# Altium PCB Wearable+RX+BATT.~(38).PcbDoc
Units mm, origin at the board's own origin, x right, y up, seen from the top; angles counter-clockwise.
Board outline 26 x 26 mm, 2 copper layers (Top, Bottom), stack 0.323 mm thick; 66 components, 48 nets, 228 pads, 162 vias.
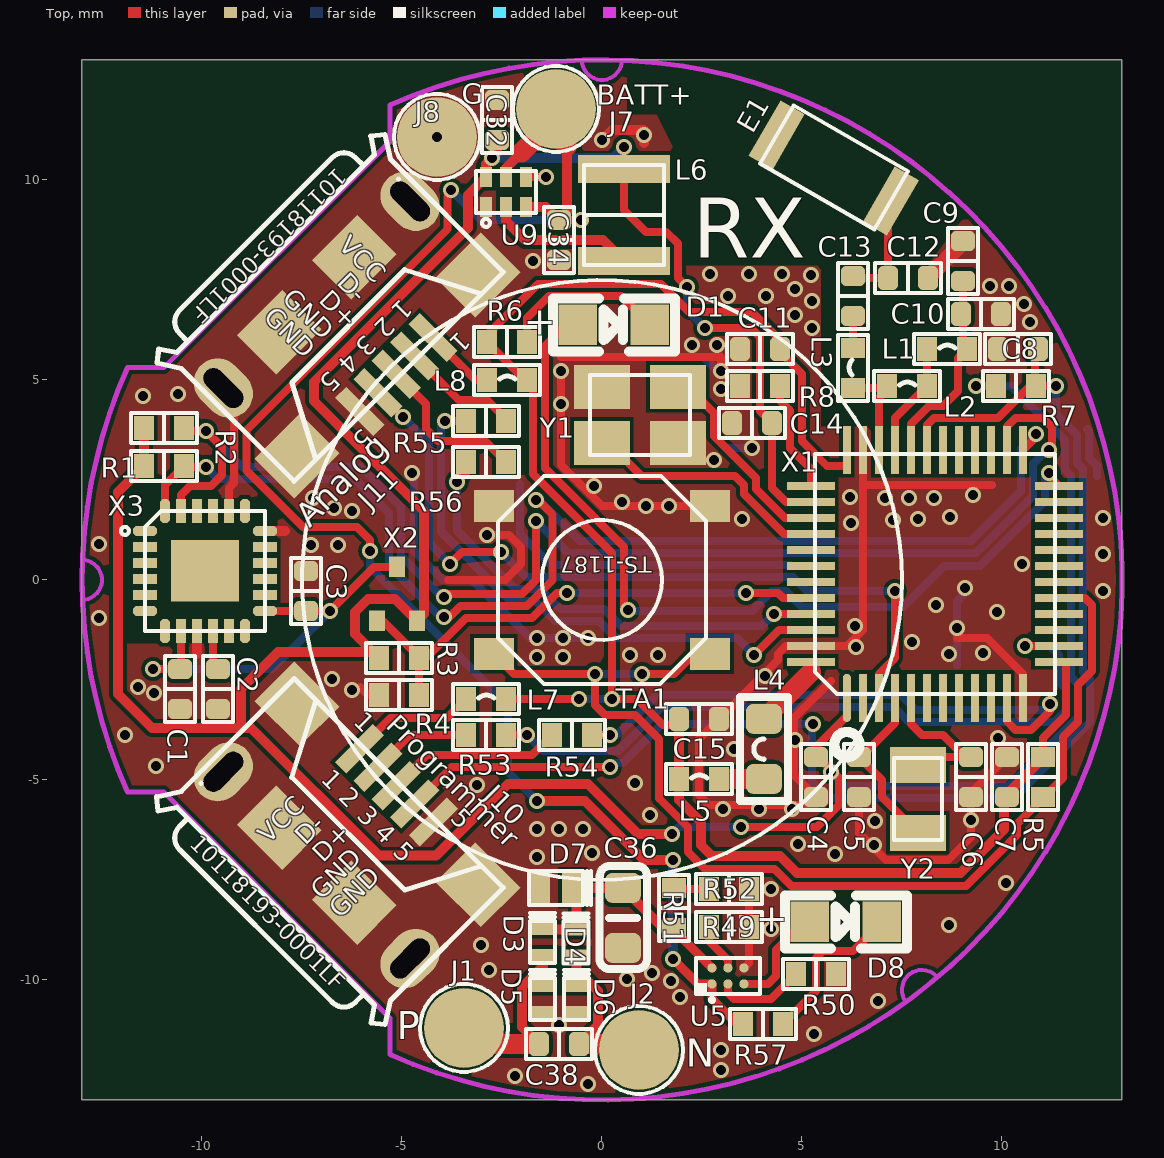
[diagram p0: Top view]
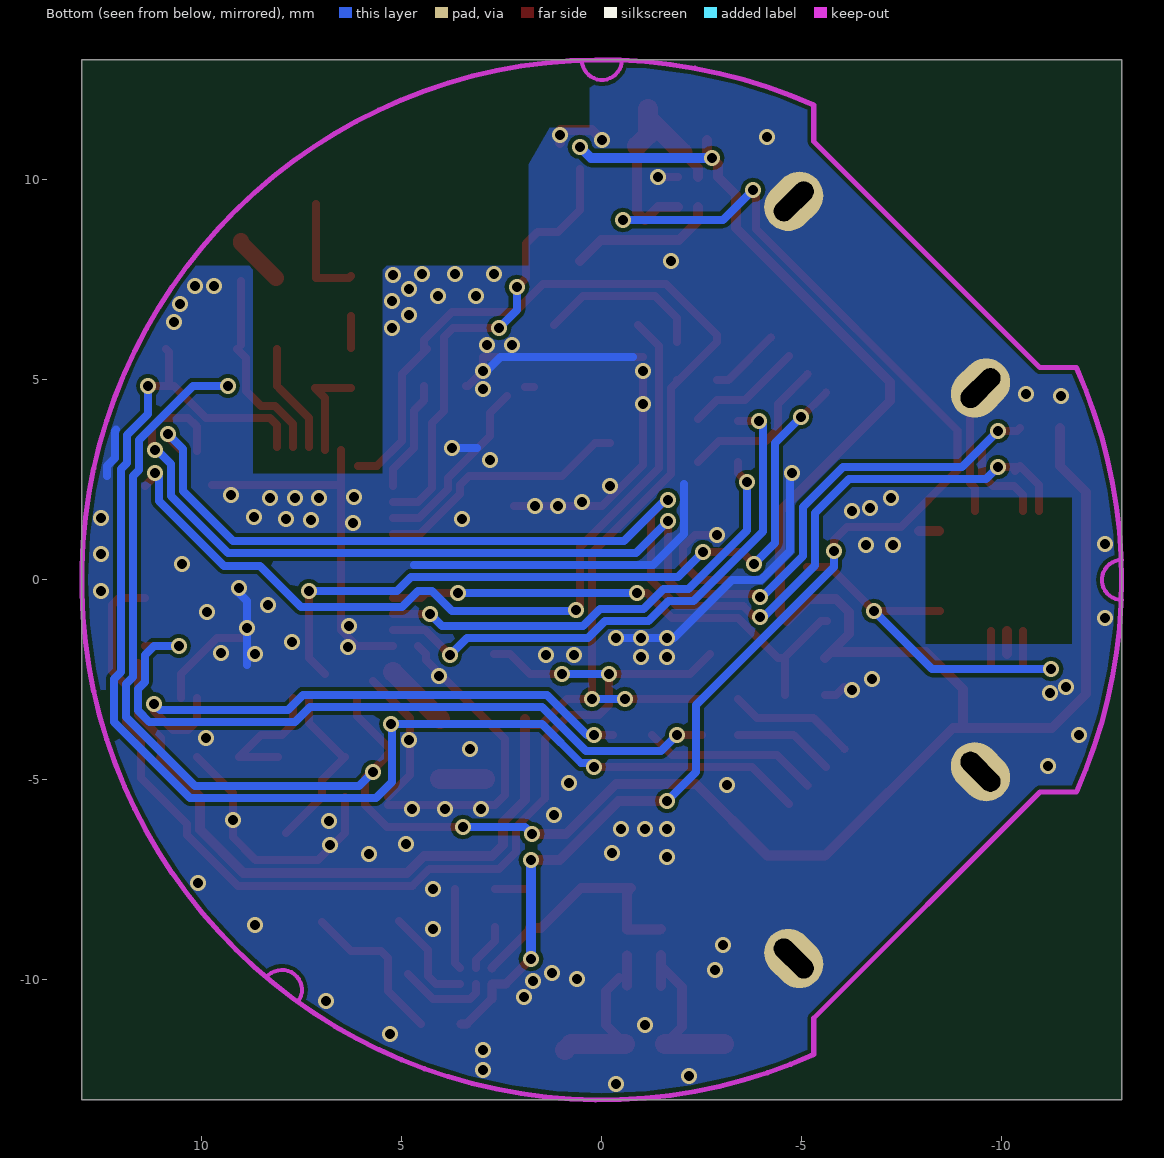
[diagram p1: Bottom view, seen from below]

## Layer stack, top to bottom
Top: signal copper 0.0343
Dielectric: core 0.254, FR-4, Dk 4.3
Bottom: signal copper 0.0343

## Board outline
-13,-13 13,-13 13,-5.875 13,13 -13,13 -13,-13

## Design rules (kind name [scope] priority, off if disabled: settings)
Clearance [All] p1: gap=0.1
Clearance "'Default' PADS rule_18" [All] p2: gap=0.152
Clearance "'Default' PADS rule_15" [IsVia vs IsVia] p3: gap=0.152
ComponentClearance "'Default' PADS rule_12" [All] p1 off: gap=0 collisioncheckmode=3 verticalgap=0 showdistances=FALSE
DiffPairsRouting [All] p1 off: maxlimit=0.254 minlimit=0.254 mostfreqgap=0.254 maxuncoupledlength=12.7
FabricationTestPointUsage TestPointUsage [All] p1 off: valid=0 allowmultiple=FALSE
FabricationTestpoint Testpoint [(IsPad And (OnTopLayer Or OnBottomLayer))] p1 off: side=3 testpointundercomponent=TRUE minsize=1.016 maxsize=2.54 preferedsize=1.524 minholesize=0 maxholesize=1.016 preferedholesize=0.813 testpointgrid=0.025 allowsidetop=TRUE allowsidebottom=TRUE usegrid=TRUE gridtolerance=0
FanoutControl Fanout_BGA [IsBGA] p1 off: bgadir=Out bgaviamode=Centered fanoutstyle=Auto fanoutdirection=Alternating viagrid=0.025 // Fanout_BGA (Default Rule)
FanoutControl Fanout_LCC [IsLCC] p2 off: bgadir=Out bgaviamode=Centered fanoutstyle=Auto fanoutdirection=Alternating viagrid=0.025 // Fanout_LCC (Default Rule)
FanoutControl Fanout_SOIC [IsSOIC] p3 off: bgadir=Out bgaviamode=Centered fanoutstyle=Auto fanoutdirection=Alternating viagrid=0.025 // Fanout_SOIC (Default Rule)
FanoutControl Fanout_Small [(CompPinCount < 5)] p4 off: bgadir=Out bgaviamode=Centered fanoutstyle=Auto fanoutdirection=OutThenIn viagrid=0.025 // Fanout_Small (Default Rule)
FanoutControl Fanout_Default [All] p5 off: bgadir=Out bgaviamode=Centered fanoutstyle=Auto fanoutdirection=Alternating viagrid=0.025 // Fanout_Default (Default Rule)
FlightTimeFalling "'Default' PADS rule_10" [All] p1 off: maximum=10.00
FlightTimeRising "'Default' PADS rule_9" [All] p1 off: maximum=10.00
Height [All] p1 off: minheight=0 maxheight=25.4 prefheight=12.7
HoleSize [All] p1 off: absolutevalues=TRUE maxlimit=2.54 minlimit=0.025 maxpercent=80.000 minpercent=20.000
LayerPairs [All] p1 off: enforce=TRUE
Length "'Default' PADS rule_5" [All] p1 off: maxlimit=1270 minlimit=0
MatchedLengths "'Default' PADS rule_11" [InNetClass('All Nets')] p1 off: tolerance=5.08 checknetsindiffpair=TRUE checkdiffpairvsdiffpair=TRUE checkothers=TRUE
MaxMinImpedance "'Default' PADS rule_8" [All] p1 off: minimum=50.00 maximum=150.0
ParallelSegment "'Default' PADS rule_7" [All] p1 off: limit=25.4 gap=5.08
ParallelSegment "'Default' PADS rule_6" [All] p2 off: limit=25.4 gap=5.08
PasteMaskExpansion [All] p1 off: expansion=0
PlaneClearance "'Default' PADS rule_14" [All] p1 off: clearance=0.152
PlaneConnect "Power Plane Connect Style - from global settings" [All] p1: planeconnectstyle=Direct reliefexpansion=0.508 reliefentries=2 reliefconductorwidth=0.381 reliefairgap=0.254
PolygonConnect [All] p1: connectstyle=Direct reliefconductorwidth=0.254 reliefentries=4 polygonreliefangle="90 Angle" airgapwidth=0.254
RoutingCorners [All] p1 off: cornerstyle=45-Degree minsetback=2.54 maxsetback=2.54
RoutingLayers "'Default' PADS rule_3" [All] p1 off: top layer_v5=TRUE bottom layer_v5=TRUE
RoutingPriority "'Default' PADS rule_2" [All] p1 off: routingpriority=3
RoutingTopology "'Default' PADS rule" [All] p1 off: topology=Shortest
RoutingVias "'Default' PADS rule_4" [All] p1: holewidth=0.94 width=0.4 viastyle="Through Hole" minholewidth=0.2 minwidth=0.3 maxholewidth=2 maxwidth=1.397
SMDToCorner "'Default' PADS rule_16" [All] p1 off: distance=60000
SMDToPlane "'Default' PADS rule_17" [All] p1 off: distance=60000
SolderMaskExpansion [All] p1 off: expansion=0.102
Width "'Default' PADS rule_13" [All] p1: maxlimit=0.6 minlimit=0.1 preferedwidth=0.2
9 further rules are at their usual default settings.

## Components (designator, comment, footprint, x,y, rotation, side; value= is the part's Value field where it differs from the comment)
C1 "10nF" 0402C -10.55,-2.725 r270 top
C2 "0.1uF" 0402C -9.6,-2.725 r270 top
C3 "0.1uF" 0402C -7.4,-0.275 r270 top
C4 "100nF" 0402C 5.35,-4.925 r90 top
C5 "22pF" 0402C 6.425,-4.925 r90 top
C6 "22pF" 0402C 9.225,-4.925 r90 top
C7 "100nF" 0402C 10.125,-4.925 r90 top
C8 "100nF" 0402C 10.4,5.775 r180 top
C9 "22nF" 0402C 9.025,7.975 r90 top
C10 "8.2nF" 0402C 9.475,6.65 r0 top
C11 "100nF" 0402C 3.95,5.775 r180 top
C12 "1pF" 0402C 7.65,7.55 r0 top
C13 "1.5pF" 0402C 6.275,7.1 r90 top
C14 "100nF" 0402C 3.75,3.925 r0 top
C15 "1uF" 0402C 2.425,-3.475 r180 top
C32 "4.7uF" 0402C -2.625,11.5 r90 top
C34 "2.2uF" 0402C -1.075,8.5 r270 top
C36 "22uF" 0603CS 0.525,-8.45 r270 top
C38 "8.2nF" 0402C -1.075,-11.6 r0 top
D1 "BLUE" 0603D 0.3,6.375 r0 top
D3 "Schottky_1PS10SB82" SOD882 -1.475,-9.05 r90 top
D4 "Schottky_1PS10SB82" SOD882 -0.631,-9.069 r90 top
D5 "Schottky_1PS10SB82" SOD882 -1.475,-10.475 r90 top
D6 "Schottky_1PS10SB82" SOD882 -0.625,-10.475 r90 top
D7 "Zener_CZRER52C6V2" 1308D -1.15,-7.7 r0 top
D8 "RED" 0603D 6.1,-8.55 r0 top
E1 "Antenna" 3216 5.796,10.3 r150 top
J1 "COIL_P" PAD -3.45,-11.2 r90 top
J2 "COIL_N" PAD 0.925,-11.75 r90 top
J7 "BT+" PAD -1.15,11.775 r90 top
J8 "BT-" PAD -4.125,11.075 r90 top
J10 "10118193-0001LF" 10118193-0001LF -8.65,-8.65 r315 top locked
J11 "10118193-0001LF" 10118193-0001LF -8.65,8.65 r225 top locked
L1 "6.2nH" 0402L 8.625,5.775 r0 top
L2 "1.1nH" 0402L 7.625,4.85 r0 top
L3 "2.2nH" 0402L 6.275,5.3 r90 top
L4 "10uH" 0603LS 4.05,-4.225 r90 top
L5 "15nH" 0402L 2.425,-4.975 r0 top
L6 "2.2uH-MIPF2520D2R2" 2520 0.55,9.125 r270 top
L7 "0nH" 0402L -2.9,-2.975 r0 top
L8 "0nH" 0402L -2.375,5 r0 top
R1 "10K" 0402R -10.95,2.85 r180 top
R2 "10K" 0402R -10.95,3.8 r180 top
R3 "NC" 0402R -5.075,-1.95 r0 top
R4 "47K" 0402R -5.075,-2.875 r180 top
R5 "10K" 0402R 11.025,-4.925 r270 top
R6 "1K" 0402R -2.375,5.95 r180 top
R7 "100K" 0402R 10.35,4.85 r0 top
R8 "56K" 0402R 3.95,4.85 r0 top
R49 "5.6K" 0402R 3.175,-8.675 r0 top
R50 "10K" 0402R 5.35,-9.85 r0 top
R51 "200K" 0402R 1.8,-8.2 r270 top
R52 "100k" 0402R 3.175,-7.725 r180 top
R53 "0" 0402R -2.9,-3.875 r180 top
R54 "0" 0402R -0.75,-3.875 r180 top
R55 "0" 0402R -2.9,3.975 r0 top
R56 "0" 0402R -2.9,2.95 r0 top
R57 "1K" 0402R 4.025,-11.1 r0 top
TA1 "TS-1187" TS-1187 0,0 r180 top
U5 "BQ25101" XBGA-N6-BQ25101 3.15,-9.9 r270 top
U9 "TPS62230" USON6-TPS62230 -2.4,9.7 r90 top
X1 "QN_9020" QUAD48 8.325,0.15 r90 top
X2 "DMG1012T" SOT523 -5.125,-0.125 r0 top
X3 "MPU_9250" QFN24-MPU9250 -9.925,0.225 r0 top
Y1 "20MHz" FA-20H 0.95,4.125 r180 top
Y2 "FC-12M 32.768 kHz" FC-12M 7.9,-5.475 r270 top

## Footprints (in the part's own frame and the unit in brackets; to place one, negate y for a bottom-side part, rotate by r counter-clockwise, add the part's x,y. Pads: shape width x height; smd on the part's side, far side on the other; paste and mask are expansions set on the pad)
0402C [mm]
  rrect50% 0.5x0.6 smd: 1(-0.5,0) 2(0.5,0)
  silkscreen extent -0.82,-0.38 0.82,0.38
0402L [mm]
  rect 0.5x0.6 smd: 1(-0.5,0) 2(0.5,0)
  silkscreen extent -0.82,-0.38 0.82,0.38
0402R [mm]
  rect 0.5x0.6 smd: 1(-0.5,0) 2(0.5,0)
  silkscreen extent -0.82,-0.38 0.82,0.38
0603CS [mm]
  rrect50% 0.75x0.9 smd: 1(-0.75,0) 2(0.75,0)
  silkscreen extent -1.3,-0.58 1.28,0.6
0603D [mm]
  rect 0.965x1.016 smd: 1(-0.9,0) 2(0.9,0)
  silkscreen extent -1.52,-0.66 1.52,0.66
0603LS [mm]
  rrect50% 0.75x0.9 smd: 1(-0.75,0) 2(0.75,0)
  silkscreen extent -1.3,-0.6 1.3,0.6
1308D [mm]
  rect 0.55x0.85 smd: 1(-0.425,0) 2(0.425,0)
  silkscreen extent -0.67,-0.43 0.87,0.43
2520 [mm]
  rect 0.7x2.3 smd: 1(-1.15,0) 2(1.15,0)
  silkscreen extent -1.25,-1 1.25,1
3216 [mm]
  rect 0.7x1.6 smd: 1(-1.65,0) 2(1.65,0)
  silkscreen extent -1.65,-0.85 1.65,0.83
10118193-0001LF [mm]
  rect 0.4x1.35 smd: 1(-1.3,4.963) 2(-0.65,4.963) 3(0,4.961) 4(0.65,4.963) 5(1.3,4.975)
  rect 1.6x1.4 smd: 6(-3.2,4.65) 7(3.2,4.65) 8(1.325,2.15) 9(-1.325,2.15)
  oval 1.2x1.6 hole 0.5 slot 1.2 at 90 deg: 8(3.3,2.15) 9(-3.3,2.15)
  silkscreen extent -4.04,0 4.03,5.05
FA-20H [mm] "Crystal Oscilator 12-48 MHZ"
  rect 1.4x1.1 smd: 1(-0.95,-0.7) 2(0.95,-0.7) 3(0.95,0.7) 4(-0.95,0.7)
  silkscreen extent -1.25,-1 1.25,1
FC-12M [mm] "32.768 kHz Crystal"
  rect 0.9x1.4 smd: 1(-0.85,0) 2(0.85,0)
  silkscreen extent -1.02,-0.6 1.02,0.6
PAD [mm]
  round 2 smd: 1(0,0)
QFN24-MPU9250 [mm]
  oct 0.6x0.25 smd: 1(-1.5,1) 6(-1.5,-1) 13(1.5,-1) 18(1.5,1)
  rect 0.6x0.25 smd: 2(-1.5,0.6) 3(-1.5,0.2) 4(-1.5,-0.2) 5(-1.5,-0.6) 14(1.5,-0.6) 15(1.5,-0.2) 16(1.5,0.2) 17(1.5,0.6)
  oct 0.25x0.6 smd: 7(-1,-1.5) 12(1,-1.5) 19(1,1.5) 24(-1,1.5)
  rect 0.25x0.6 smd: 8(-0.6,-1.5) 9(-0.2,-1.5) 10(0.2,-1.5) 11(0.6,-1.5) 20(0.6,1.5) 21(0.2,1.5) 22(-0.2,1.5) 23(-0.6,1.5)
  rect 1.7x1.54 smd: 25(0,0)
  silkscreen extent -2.1,-1.5 1.5,1.5
QUAD48 [mm]
  oval 1.2x0.2 smd: 1(-3.1,2.2)
  rect 1.2x0.2 smd: 2(-3.1,1.8) 3(-3.1,1.4) 4(-3.1,1) 5(-3.1,0.6) 6(-3.1,0.2) 7(-3.1,-0.2) 8(-3.1,-0.6) 9(-3.1,-1) 10(-3.1,-1.4) 11(-3.1,-1.8) 12(-3.1,-2.2) 25(3.1,-2.2) 26(3.1,-1.8) 27(3.1,-1.4) 28(3.1,-1) 29(3.1,-0.6) 30(3.1,-0.2) 31(3.1,0.2) 32(3.1,0.6) 33(3.1,1) 34(3.1,1.4) 35(3.1,1.8) 36(3.1,2.2)
  rect 0.2x1.2 smd: 13(-2.2,-3.1) 14(-1.8,-3.1) 15(-1.4,-3.1) 16(-1,-3.1) 17(-0.6,-3.1) 18(-0.2,-3.1) 19(0.2,-3.1) 20(0.6,-3.1) 21(1,-3.1) 22(1.4,-3.1) 23(1.8,-3.1) 24(2.2,-3.1) 37(2.2,3.1) 38(1.8,3.1) 39(1.4,3.1) 40(1,3.1) 41(0.6,3.1) 42(0.2,3.1) 43(-0.2,3.1) 44(-0.6,3.1) 45(-1,3.1) 46(-1.4,3.1) 47(-1.8,3.1) 48(-2.2,3.1)
  silkscreen extent -4.58,-3 3,3
SOD882 [mm]
  rect 0.3x0.55 smd: 1(-0.325,0) 2(0.325,0)
  silkscreen extent -0.53,-0.3 0.72,0.33
SOT523 [mm]
  rect 0.4x0.51 smd: D(0,0.45) G(-0.5,-0.9) S(0.5,-0.9)
TS-1187 [mm]
  rect 1x0.8 smd: 1(-2.7,1.85) 2(2.7,1.85) 3(-2.7,-1.85) 4(2.7,-1.85)
  silkscreen extent -2.6,-2.6 2.6,2.6
USON6-TPS62230 [mm]
  rect 0.5x0.3 smd: 1(-0.375,0.5) 2(-0.375,0) 3(-0.375,-0.5) 4(0.375,-0.5) 5(0.375,0) 6(0.375,0.5)
  silkscreen extent -0.87,-0.75 0.53,0.75
XBGA-N6-BQ25101 [mm]
  round 0.23 smd: A1(0.2,-0.4) A2(-0.2,-0.4) B1(0.2,0) B2(-0.2,0) C1(0.2,0.4) C2(-0.2,0.4)
  silkscreen extent -0.45,-0.8 0.65,0.8

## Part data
C1 C2 C3 C4 C5 C6 C7 C8 C9 C10 C11 C12 C13 C14 C15: library part "SMALL CAP"
C32 C38: library part CAP_CER_4.7uf_0603
C34 C36: library part CAP_2.2nF_X7R_0603
D1 D8: library part LED
D3 D4 D5 D6: library part SchottkyDiode_1PS10SB82
D7: library part Z_Diode_CZRER52C6V2
J1 J2 J7 J8: library part CON1
J10 J11: library part 10118193-0001LF_MUSB_1
L1 L2 L3 L4 L5 L7 L8: library part INDUCTOR
L6: library part MLZ1005M2R2W_Ind402_0
R1: library part RESISTOR/SM
R2 R3 R4 R5 R6 R7 R8 R57: library part R
R49 R50 R51 R52 R53 R54 R55 R56: library part RES_10K_0603_THK_1%
TA1: library part "SW-PB 4P_1", "TACT SW"
U5: library part BQ25101_0
U9: library part TPS62232_6P_SQN
X3: library part MPU_1
Y1: library part FA-20H
Y2: library part QZP100K

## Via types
v1: diameter 0.4, hole 0.25, Top to Bottom, tented both sides, 162 vias

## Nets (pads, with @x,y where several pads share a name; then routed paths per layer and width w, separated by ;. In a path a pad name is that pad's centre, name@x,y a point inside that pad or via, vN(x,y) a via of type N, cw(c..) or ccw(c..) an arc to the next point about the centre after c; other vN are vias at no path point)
ACCEL_CONTROL: R3.2 R4.1 X1.44 X2.G | length 12.9
  Top w0.2: X2.G -5.475,-1.025 -4.575,-1.925 R4.1 ; R3.2 -4.4,-1.95 -3.4,-0.95 -1.75,-0.95 -1.125,-0.325 v1(-0.875,-0.325) ; v1(3.6,-0.325) 4.4,-0.325 4.525,-0.45 X1.44
  Bottom w0.2: v1(-0.875,-0.325) v1(3.6,-0.325)
ACCEL_INTR: X3.12
ACCEL_VCC: C1.1 C3.2 X2.D X3.8 X3.13 | length 10.4
  Top w0.2: v1(-11.225,-2.225) C1.1 ; C1.1@-10.525,-2.2 X3.8 ; X3.13@-8.45,-0.775 v1(-6.8,-0.775) -5.7,0.325 X2.D
  Bottom w0.2: v1(-11.225,-2.225) -8.25,-2.225 v1(-6.8,-0.775)
AIN0: R55.1 X1.46 | length 14.1
  Top w0.2: v1(-3.925,3.975) R55.1 ; v1(3.8,-1.875) 4.425,-1.25 X1.46
  Bottom w0.2: v1(-3.925,3.975) -4.025,3.875 -4.025,1.21 -2.29,-0.525 -1.665,-0.525 -1.165,-1.025 -0.075,-1.025 0.35,-1.45 3.375,-1.45 v1(3.8,-1.875)
AIN1: R56.1 X1.45 | length 11.8
  Top w0.2: v1(-3.625,2.45) -3.4,2.675 R56.1 ; v1(4.3,-0.85) X1.45
  Bottom w0.2: v1(-3.625,2.45) -3.625,1.234 -2.166,-0.225 -1.541,-0.225 -1.041,-0.725 0.049,-0.725 0.474,-1.15 4,-1.15 v1(4.3,-0.85)
AIN2: J11.4 X1.3 | length 18.9
  Top w0.2: J11.4 v1@-4.985,4.065 ; v1(-3.8,0.4) -3.5,0.7 v1(-2.525,0.7) ; 6.925,-2.35 7.325,-1.95 v1(7.325,-0.275)
  Bottom w0.2: v1(-4.975,4.075) -4.325,3.425 -4.325,0.925 v1(-3.8,0.4) ; v1(-2.525,0.7) -1.9,0.075 4.775,0.075 5.125,-0.275 6.125,-0.275 v1(7.325,-0.275)
AIN3: X1.2
ANTENNA: C12.1 C13.2 E1.1 | length 2.7
  Top w0.2: C13.2 6.325,7.55 C12.1 E1.1@7.15,9.4
COIL_N: C38.2 D4.1 D6.2 J2.1 | length 4.3
  Top w0.25: D6.2@-0.631,-10.144 D4.1 ; C38.2 -0.1,-11.125 -0.1,-10.275 -0.425,-9.95
  Top w0.5: C38.2 0.775,-11.6 J2.1
COIL_P: C38.1 D3.1 D5.2 J1.1 | length 4.6
  Top w0.25: C38.1 -2,-11.175 -2,-10.175 -1.475,-9.65 ; D5.2 -1.475,-9.65 ; D3.1 -1.475,-9.65
  Top w0.5: J1.1@-3.05,-11.6 C38.1
GND: C1.2 C2.2 C3.1 C4.1 C5.1 C6.1 C7.2 C8.2 C9.2 C10.2 C11.2 C12.2 C14.1 C15.1 C32.2 C34.2 C36.2 D5.1 D6.1 D7.1 J8.1 J10.5 J10.6 J10.7 J10.8 J10.9 J11.5 J11.6 J11.7 J11.8 J11.9 R4.2 R8.1 R49.2 R50.2 R52.1 TA1.3 TA1.4 U5.C2 U9.1 U9.4 X1.12 X1.35 X1.47 X3.9 X3.18 X3.20 Y1.2 Y1.4 | length 76.9
  Top w0.2: X3.20 -9.325,2.3 -9.2,2.425 J11.8@-9.2,4.533 ; -6.05,-2.675 -5.85,-2.875 R4.2 ; -3.85,0 -2.425,0 -2.025,0.4 -2.025,0.825 -2.325,1.125 v1(-2.875,1.125) ; U9.4 v1(-1.4,10.075) ; v1(-1.025,5.225) -1.025,2.875 0,1.85 2.2,1.85 ; -1.025,5.575 2.975,5.575 ; 2.975,5.5 v1(2.975,5.225) 3.35,4.85 R8.1@3.4,4.85 ; U5.C2 3.675,-9.575 R52.1 ; 4.6,-1.65 4.4,-1.85 4.4,-2 C15.1 2.425,-3.975 2.425,-5.375 2.675,-5.625 C4.1@5.35,-5.625 ; X1.47 6.125,-1.65 6.525,-1.25 6.525,2.375 ; C4.1 4.8,-4.875 4.8,-3.45 5.725,-2.525 ; C5.1 6.425,-6.325 7.1,-7 8.658,-7 9.225,-6.433 C6.1 9.225,-5.325 C7.2 ; X1.35 6.525,2.375 ; 8.875,-1.45 9.625,-1.45 10.525,-2.35 X1.12 ; 9.75,2.375 6.525,2.375
  Top w0.25: -10.125,-1.85 X3.9 ; X3.18 -7.925,1.225 ; v1(0,11) 0.25,11.25 1.038,11.25 1.05,11.238 1.05,10.925
  Top w0.4: C12.2 9.025,8.425 C9.2
  Bottom w0.2: v1@-4.7,2.675 -4.7,0.725 -3.975,0 -3.25,0 -1.8,-1.45 v1(-0.35,-1.45) ; -2.05,2.4 -2.05,1.15 -1.275,0.375 4.7,0.375 ; -0.775,5.575 2.539,5.575 2.889,5.225 v1(2.975,5.225) ; 3.125,3.3 v1(3.75,3.3) ; 8.875,-2.125 8.875,-0.524 v1@9.149,-0.25 ; 12.146,3.754 12.175,3.725 12.175,3.05 12.375,2.85 12.375,2.6
  other v1: -0.35,-12.6 -2.175,-12.4 2.975,-12.25 2.975,-11.75 5.3,-11.35 -1.075,-11.125 6.9,-10.525 1.95,-10.425 1.725,-10.025 0.625,-9.975 1.25,-9.825 -2.825,-9.75 -3.025,-9.125 4.225,-8.725 8.675,-8.625 4.225,-7.725 10.1,-7.575 -1.625,-6.925 5.825,-6.85 -0.25,-6.825 6.8,-6.625 4.9,-6.6 -1.625,-6.225 -1.075,-6.225 -0.475,-6.225 6.825,-6.025 9.225,-6 1.2,-5.875 3.025,-5.725 3.925,-5.725 4.75,-5.725 -3.125,-5.125 0.825,-5.075 -11.15,-4.65 3.3,-4.225 4.825,-4 9.9,-3.95 -11.925,-3.875 -11.2,-2.825 -6.25,-2.75 -11.6,-2.675 -6.75,-2.475 4.075,-2.4 -1.625,-1.925 -0.975,-1.925 0.7,-1.875 1.4,-1.875 8.675,-1.85 9.525,-1.825 6.35,-1.675 7.75,-1.55 -1.625,-1.45 -0.975,-1.45 8.875,-1.2 6.325,-1.15 -12.575,-0.95 9.875,-0.8 8.35,-0.625 12.525,-0.275 9.075,-0.2 10.5,0.4 12.525,0.65 -7.275,0.875 -6.6,0.875 -12.575,0.9 6.225,1.425 7.275,1.5 3.5,1.525 7.9,1.525 12.525,1.55 8.7,1.575 -6.25,1.725 -6.7,1.8 1.1,1.85 1.675,1.85 0.5,1.95 -7.225,2.05 7.075,2.05 7.675,2.05 8.3,2.05 6.2,2.075 9.275,2.125 -0.2,2.35 -4.75,2.675 2.8,3 -1.025,4.4 -11.475,4.6 -10.6,4.65 2.975,4.775 2.25,5.875 2.875,5.875 5.25,6.3 10.7,6.45 4.825,6.625 10.55,6.9 5.25,6.975 3.15,7.1 4.1,7.1 4.825,7.275 9.7,7.35 10.175,7.35 5.225,7.625 2.7,7.65 3.675,7.65 4.5,7.65 -1.725,7.975 -4.125,11.075 1.05,11.125
I2C-SCL: R1.1 X1.25 X3.24 | length 30.8
  Top w0.2: X3.24 -10.925,2.375 R1.1 R1.1@-10.425,2.825 ; R1.1@-10.325,2.725 R1.1@-10.425,2.825 ; v1(-9.9,2.825) R1.1@-10.425,2.825 ; v1(-3.95,-0.925) -3.809,-0.925 -3.534,-0.65 -1.876,-0.65 -1.233,-0.007 -1.233,1.633 v1@-1.625,2.025 ; X1.25 10.85,3.575 v1(10.85,3.65)
  Bottom w0.2: v1(-9.9,2.825) -9.6,2.525 -6.175,2.525 -5.325,1.675 -5.325,0.36 -4.04,-0.925 v1(-3.95,-0.925) ; v1@-1.6,1.95 v1(-1.65,2) -1.575,2 -0.55,0.975 9.225,0.975 10.475,2.225 10.475,3.275 v1(10.85,3.65)
I2C-SDA: R2.1 X1.26 X3.23 | length 32.6
  Top w0.2: X3.23 -10.525,2.125 -10.3,2.35 -9.775,2.35 -9.5,2.625 -9.5,3.325 v1(-9.9,3.725) -10.375,3.725 R2.1 ; v1(-3.95,-0.425) -3.875,-0.35 -2,-0.35 -1.65,0 v1(-1.65,1.475) ; X1.26@10.125,3.225 10.125,3.833 10.342,4.05 11.025,4.05 11.25,3.825 v1@11.25,3.375
  Bottom w0.2: v1(-9.9,3.725) -9,2.825 -6.025,2.825 -5.025,1.825 -5.025,0.6 v1@-4.05,-0.375 ; v1(-1.65,1.475) -0.85,0.675 9.349,0.675 10.775,2.101 10.775,2.9 v1@11.075,3.2
  other v1: 11.175,3.25
NetC2_1: C2.1 X3.10 | length 0.8
  Top w0.2: C2.1@-9.725,-2.1 X3.10
NetC5_2: C5.2 X1.4 Y2.2 | length 4.3
  Top w0.2: C5.2 7,-5 7,-5.425 Y2.2 ; C5.2@6.475,-4.425 7.325,-3.575 X1.4
NetC6_2: C6.2 X1.5 Y2.1 | length 3.3
  Top w0.2: X1.5 7.725,-3.6 8,-3.875 8.525,-3.875 9.075,-4.425 Y2.1@8.1,-4.425
NetC9_1: C9.1 C10.1 L1.2 X1.32 | length 4.8
  Top w0.2: X1.32@7.725,3.325 7.725,3.9 8.175,4.35 8.525,4.35 8.9,4.725 8.9,5.55 L1.2 ; L1.2@9.025,5.875 C9.1
NetC13_1: C13.1 L3.2 | length 0.8
  Top w0.2: L3.2 C13.1
NetC36_1: C36.1 D3.2 D4.2 D7.2 R51.2 U5.A2 | length 6.3
  Top w0.23: R51.2@1.8,-8.75 U5.A2
  Top w0.25: D3.2 -1.456,-8.744 D4.2 -0.631,-7.794 D7.2 C36.1 1.525,-8.7 R51.2 R51.2@1.8,-8.75
NetD1_1: D1.1 X1.24 | length 21.2
  Top w0.2: D1.1@-0.9,6.375 -1.425,5.85 -1.425,2.8 0.55,0.825 0.55,-0.625 v1@0.65,-0.725 ; v1(11.175,2.675) 11.175,2.6 X1.24
  Bottom w0.2: v1@0.65,-0.775 3.75,-0.775 4.25,-0.275 4.6,-0.275 5,-0.675 7.525,-0.675 8.55,0.35 9.449,0.35 11.075,1.976 11.075,2.575 v1(11.175,2.675)
  other v1: 0.65,-0.75
NetD1_2: D1.2 R6.1 | length 4.2
  Top w0.2: R6.1 -1.875,6.55 -1.325,7.1 0.475,7.1 D1.2
NetD8_1: D8.1 U5.C1 | length 2.6
  Top w0.2: U5.C1 4.15,-10.1 4.35,-9.9 4.35,-9.25 D8.1@5.075,-8.525
NetD8_2: D8.2 R57.2 | length 4
  Top w0.2: R57.2 5.35,-10.275 5.35,-9.45 5.525,-9.275 6.275,-9.275 D8.2
NetJ10_1: J10.1 L7.1 | length 3.2
  Top w0.2: J10.1 -5.288,-3.45 -3.875,-3.45 L7.1
NetJ10_2: J10.2 R53.2 | length 2.5
  Top w0.2: J10.2 -4.794,-3.875 R53.2
NetJ10_3: J10.3 R54.2 | length 4.4
  Top w0.2: J10.3 -4.375,-4.375 -1.75,-4.375 R54.2
NetJ11_1: J11.1 L8.1 | length 1.8
  Top w0.2: J11.1 -3.162,5 L8.1
NetJ11_2: J11.2 R55.2 | length 2.9
  Top w0.2: J11.2 -3.581,4.5 -2.875,4.5 R55.2@-2.4,4.025
NetJ11_3: J11.3 R56.2 | length 4
  Top w0.2: J11.3 -4.4,4.4 -4.4,3.775 -4.1,3.475 -2.925,3.475 R56.2
NetL1_1: L1.1 L2.2 X1.33 | length 2.7
  Top w0.2: X1.33@7.325,3.325 7.325,4.05 L2.2@8.075,4.8 ; L2.2 L1.1
NetL2_1: L2.1 L3.1 X1.34 | length 2.6
  Top w0.2: L3.1 7.175,4.8 6.925,4.55 X1.34
NetL4_1: L4.1 L5.2 | length 1.1
  Top w0.5: L5.2 L4.1
NetL4_2: L4.2 X1.48 | length 1.7
  Top w0.5: L4.2 5.225,-2.3
NetL6_2: L6.2 U9.2 | length 3.7
  Top w0.25: U9.2 -2.4,8.975 -1.925,8.5 0.025,8.5 L6.2
NetR5_2: R5.2 TA1.1 TA1.2 X1.17 | length 28.2
  Top w0.2: TA1.2 -2.2,-2.35 v1(-0.175,-2.35) -0.175,-3.125 0.075,-3.375 0.825,-3.375 1.425,-3.975 1.425,-5.459 2.15,-6.184 2.15,-6.8 2.575,-7.225 4.315,-7.225 4.74,-7.65 9.1,-7.65 10.375,-6.375 10.375,-6.1 11.525,-4.95 11.525,-3.925 11.9,-3.55 11.9,-2.625 12.25,-2.275 12.25,-0.625 12.075,-0.45 X1.17 ; v1(1,-2.35) 1.8,-2.35 2.3,-1.85 TA1.1
  Bottom w0.2: v1(-0.175,-2.35) v1(1,-2.35)
NetR8_2: R8.2 X1.37 | length 2.8
  Top w0.2: R8.2 4.45,4.485 4.7,4.235 4.7,3.3 5.225,2.775 X1.37
NetR49_1: R49.1 U5.B2 | length 1.2
  Top w0.2: R49.1 2.675,-9.025 3.15,-9.5 U5.B2
NetR50_1: R50.1 U5.B1 | length 2.2
  Top w0.2: U5.B1 3.15,-10.325 3.3,-10.475 4.225,-10.475 R50.1
NetR51_1: R51.1 R52.2 | length 0.9
  Top w0.2: R51.1 1.825,-7.725 R52.2
NetX1_39: X1.39 Y1.1 | length 4.8
  Top w0.2: Y1.1@1.7,4.825 Y1.1@1.925,4.825 ; Y1.1@2.375,4.6 2.8,4.175 2.8,3.6 3.85,2.55 3.85,2.274 4.574,1.55 X1.39
NetX1_40: X1.40 Y1.3 | length 6.5
  Top w0.2: Y1.3@-0.2,3.425 0.175,3.425 0.175,3.417 0.992,2.6 3.325,2.6 3.55,2.375 3.55,2.15 4.55,1.15 X1.40
RESET: C8.1 J10.4 R7.2 X1.31 | length 34
  Top w0.2: J10.4 -3.756,-4.675 v1(0.2,-4.675) ; X1.31@8.125,3.325 8.125,3.876 8.299,4.05 9.9,4.05 10.7,4.85 R7.2@10.825,4.85 ; C8.1 10.825,5.7 R7.2@10.825,4.85 ; v1(11.35,4.85) R7.2@10.825,4.85
  Bottom w0.2: v1(0.2,-4.675) 0.293,-4.582 0.518,-4.582 1.5,-3.6 v1(5.275,-3.6) 5.25,-3.625 5.25,-5.05 5.65,-5.45 10.3,-5.45 12.2,-3.55 12.2,-2.475 12.025,-2.3 12.025,2.775 11.875,2.925 11.875,3.625 11.35,4.15 v1(11.35,4.85)
UART0-RX: R53.1 X1.14 | length 18.3
  Top w0.2: R53.1@-2.5,-3.875 v1(-1.875,-3.875) ; v1(10.575,-1.65) X1.14
  Bottom w0.2: v1(-1.875,-3.875) -1.475,-4.275 0.401,-4.275 1.501,-3.175 7.3,-3.175 7.675,-3.55 11.316,-3.55 11.6,-3.266 11.6,-2.725 11.425,-2.55 11.425,-1.875 11.2,-1.65 v1(10.575,-1.65)
UART0-TX: R54.1 X1.11 | length 14.1
  Top w0.2: R54.1@-0.275,-3.875 v1(0.2,-3.875) ; X1.11 10.125,-3.533 10.342,-3.75 10.708,-3.75 10.716,-3.741 10.725,-3.75 v1@11.2,-3.275
  Bottom w0.2: v1(0.2,-3.875) 0.376,-3.875 1.376,-2.875 7.475,-2.875 7.85,-3.25 11.05,-3.25 v1(11.2,-3.1)
VBAT_P: C34.1 J7.1 R57.1 U5.A1 U9.3 U9.5 | length 40.2
  Top w0.2: v1(-5.8,0.725) -5.8,1 -6.125,1.325 -7.475,1.325 -8.885,2.735 -8.885,3.74 -3.855,8.77 -3.855,9.57 v1@-3.725,9.7 ; C34.1 v1(-0.525,9)
  Top w0.23: v1(1.775,-9.475) 2.4,-10.1 U5.A1 2.75,-10.475 3.375,-11.1 R57.1
  Top w0.25: U9.5 -2.4,10.3 -2.014,10.686 ; U9.3 -1.4,9.325 C34.1 -0.875,9.2 J7.1@-0.875,10.85 ; v1(-1.625,-5.525) -0.42,-5.525 1.055,-7 v1(1.775,-7)
  Top w0.5: -2.014,10.686 J7.1@-1.15,11.55 ; J7.1 J7.1@-1.15,11.55 ; J7.1@-0.875,10.85 -1.15,11.125 J7.1@-1.15,11.55
  Bottom w0.2: v1(-5.8,0.725) -5.8,0.325 -2.35,-3.125 -2.35,-4.8 v1(-1.625,-5.525) ; v1@-3.725,9.7 -3.025,9 v1(-0.525,9)
  Bottom w0.25: v1@1.775,-9.425 v1(1.775,-7) ; v1@1.8,-9.45 v1@1.825,-9.475
  other v1: -3.775,9.75
VCC: C4.2 C14.2 C32.1 L6.1 R1.2 R2.2 R3.1 R7.1 U9.6 X1.1 X1.38 X2.S | length 86.8
  Top w0.2: L6.1 0.55,9.25 1.1,8.7 1.608,8.7 1.9,8.408 1.9,7.55 v1(2.125,7.325) ; v1(2.575,6.3) 3.726,6.3 3.95,6.076 3.95,4.225 C14.2 4.25,2.3 4.6,1.95 X1.38 ; v1(3.475,-6.175) 5.375,-6.175 5.925,-5.625 5.925,-4.95 v1@5.775,-4.8 ; C4.2@5.4,-4.425 v1@5.775,-4.8 ; C4.2@5.412,-4.412 5.263,-4.262 6.125,-3.4 X1.1 ; v1(5.725,-4.8) v1@5.775,-4.8 ; v1(9.35,4.85) R7.1@9.825,4.85
  Top w0.25: R2.2 R1.2 -12.1,2.2 -12.1,-2.85 -11.25,-3.7 -9.025,-3.7 ; R3.1 R3.1@-5.725,-1.8 ; -2.9,10.4 U9.6 -3.35,9.625 -3.35,8.8 -7.2,4.95 -7.2,4.475 -4.45,1.725 -4.45,-0.85 X2.S -5.175,-0.475 -5.85,-0.475 -6.175,-0.8 -6.175,-1.35 R3.1@-5.725,-1.8 ; v1(-2.75,10.55) -2.625,10.675 C32.1 ; v1(1.75,-6.35) 0.9,-6.35 -0.35,-5.1 -2.35,-5.1 -4.145,-6.895 -5.58,-6.895 -8.775,-3.7 -9.025,-3.7 ; -9.025,-3.7 -9.025,-2.724 -8.101,-1.8 R3.1@-5.725,-1.8
  Bottom w0.2: v1(1.75,-6.35) 1.925,-6.175 v1(3.475,-6.175) ; v1(2.125,7.325) 2.125,6.75 v1(2.575,6.3) ; v1(5.725,-4.8) 6.075,-5.15 10.175,-5.15 11.9,-3.425 11.9,-2.6 11.725,-2.425 11.725,2.6 11.575,2.75 11.575,3.5 10.225,4.85 v1(9.35,4.85)
  Bottom w0.25: v1(-2.75,10.55) 0.275,10.55 v1(0.55,10.825)
VDD: C7.1 C11.1 C15.2 L5.1 L7.2 L8.2 R5.1 R6.2 X1.13 X1.36 | length 43.9
  Top w0.2: L7.2 v1(-0.575,-2.975) ; L8.2@-1.9,4.975 -1.725,4.8 -1.725,2.65 0.25,0.675 v1(0.25,-2.975) 0.875,-2.975 1.525,-3.625 C15.2@1.775,-3.625 ; L8.2 -1.925,5 R6.2 -2.875,6.125 -1.6,7.4 1.475,7.4 2.175,6.7 3.75,6.7 4.45,6 C11.1 ; C11.1@4.375,5.775 5,5.15 5,3.475 5.622,2.853 X1.36@6.1,2.853 ; R5.1@11.025,-4.45 R5.1 11.025,-3.95 11.6,-3.375 X1.13@11.6,-2.075
  Top w0.25: C15.2 L5.1 1.925,-5.5 2.475,-6.05 2.475,-6.625 2.75,-6.9 4.45,-6.9 4.875,-7.325 8.965,-7.325 10.05,-6.24 10.05,-5.425 R5.1@11.025,-4.45
  Bottom w0.2: v1(-0.575,-2.975) v1(0.25,-2.975)
VDDIO: X3.22
pads on no net: E1.2 X1.6 X1.7 X1.8 X1.9 X1.10 X1.15 X1.16 X1.18 X1.19 X1.20 X1.21 X1.22 X1.23 X1.27 X1.28 X1.29 X1.30 X1.41 X1.42 X1.43 X3.1 X3.2 X3.3 X3.4 X3.5 X3.6 X3.7 X3.11 X3.14 X3.15 X3.16 X3.17 X3.19 X3.21 X3.25

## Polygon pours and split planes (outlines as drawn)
GND on Bottom "Top Layer-No Net" (solid, remove dead copper, pour order 4): 13,-13 12.375,-13 -13,-13 -13,13 13,13 13,-13
GND on Top "Top Layer-No Net" (solid, remove dead copper, pour order 3): -13,-13 -12.375,-13 13,-13 13,13 -13,13 -13,-13

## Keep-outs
Keep-Out Layer:
  lines w0.1: -13,-0.5 ccw(c-13,0) -13,0.5 ; -0.5,13 ccw(c0,13) 0.5,13 ; 7.6,-10.55 cw(c8,-10.25) 8.39,-9.938
  lines w0.127: -11.862,-5.301 cw(c0.007,0.002) -11.862,5.305 -10.953,5.305 -5.297,10.962 -5.297,11.871 cw(c0.007,0.002) -5.297,-11.867 -5.297,-10.958 -10.953,-5.301 -11.862,-5.301

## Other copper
Top:
  pour cut-out: 1.825,12.75 0.646,12.75 0.625,12.729 0.625,11.625 1.375,11.625 1.825,10.725
  pour cut-out: 8.15,7.85 9.05,9.1 8.525,9.625 6.425,11.2 4.5,12.025 2.7,12.625 1.825,12.625 1.825,7.85
  pour cut-out: 5.475,3.825 8.725,3.825 8.725,7.85 5.475,7.85
  pour cut-out: -11.75,-1.6 -8.1,-1.6 -8.1,2.05 -11.75,2.05
Bottom:
  pour cut-out: 0.3,11.3 0.3,12.4 0.646,12.75 1.825,12.75 1.825,10.388 1.3,11.3
  pour cut-out: 10.158,7.85 9.843,8.26 9.45,8.7 9.086,9.086 8.525,9.625 6.425,11.2 4.5,12.025 2.7,12.625 1.825,12.625 1.825,7.85
  pour cut-out: -8.1,-1.6 -11.75,-1.6 -11.75,2.05 -8.1,2.05
  pour cut-out: 8.725,2.65 5.475,2.65 5.475,7.85 8.725,7.85

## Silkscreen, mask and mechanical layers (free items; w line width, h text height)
Silkscreen Top:
  circle w0.1: c0,0 r7.5
  circle w0.1: c-3.45,-11.2 r1.1
  circle w0.1: c0.925,-11.75 r1.1
  circle w0.1: c-1.15,11.775 r1.075
  circle w0.1: c-4.125,11.075 r1.075
  text "G" at -3.5,11.9 h0.5
  text "BATT+" at -0.125,11.875 h0.5
  text "RX" at 2.275,8.05 h1.5
  text "Analog" at -7.3,1.275 h0.6 r45
  text "Programmer" at -5.425,-3.675 h0.5 r315
  text "P" at -5.13,-11.487 h0.7
  text "N" at 2.1,-12.175 h0.7
Assembly Drawing Top:
  lines w0.1: -13,-0.5 ccw(c-13,0) -13,0.5 ; -0.5,13 ccw(c0,13) 0.5,13 ; 7.6,-10.55 cw(c8,-10.25) 8.39,-9.938
  lines w0.127: -11.862,-5.301 cw(c0.007,0.002) -11.862,5.305 -10.953,5.305 -5.297,10.962 -5.297,11.871 cw(c0.007,0.002) -5.297,-11.867 -5.297,-10.958 -10.953,-5.301 -11.862,-5.301
  lines w0.254: -16.508,-11.476 -16,-13 ; -16.508,11.476 -16,13 ; -16.254,-13 -15.746,-13 ; -16.254,13 -15.746,13 ; -16,-5.104 -16,-13 ; -16,5.104 -16,13 ; -15.492,-11.476 -16,-13 ; -15.492,11.476 -16,13 ; -13,-15.254 -13,-14.746 ; -11.476,-15.508 -13,-15 ; -11.476,-14.492 -13,-15 ; -5.104,-15 -13,-15 ; 5.104,-15 13,-15 ; 11.476,-15.508 13,-15 ; 11.476,-14.492 13,-15 ; 13,-15.254 13,-14.746
  text "26 (mm)" at -15.086,-4.85 h1.52 r90
  text ".Printout_Name" at -12.85,-13.975 h0.7
  text "26 (mm)" at -4.85,-15.914 h1.52
Drill Drawing:
  text ".Legend" at 13.5,-12.75 h0.7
